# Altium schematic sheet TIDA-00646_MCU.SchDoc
size 431 x 279 mm; Date: Not shown in title block; ApprovedBy: Not shown in title block; CheckedBy: Not shown in title block; Author: Not shown in title block; CompanyName: Not shown in title block; Engineer: Not shown in title block; Organization: Not shown in title block; Address1: Not shown in title block; Address2: Not shown in title block; Address3: Not shown in title block; Address4: Not shown in title block; DocumentNumber: 1; Revision: Use project parameter SCH_Rev; SheetNumber: 2; SheetTotal: 3; PageSetup: Record=PageOptions¦CenterHorizontal=True¦CenterVertical=True¦PrintScale=0.62¦XCorrection=1.00¦YCorrection=1.00¦PrintKind=0¦BorderSize=5000000¦LeftOffset=0¦BottomOffset=0¦Orientation=2¦PaperLength=2794¦PaperWidth=2159¦Scale=100¦PaperSource=7¦PrintQuality=600¦MediaType=1¦DitherType=10¦PrintScaleMode=1¦PaperKind=8 1/2x11¦PaperIndex=1
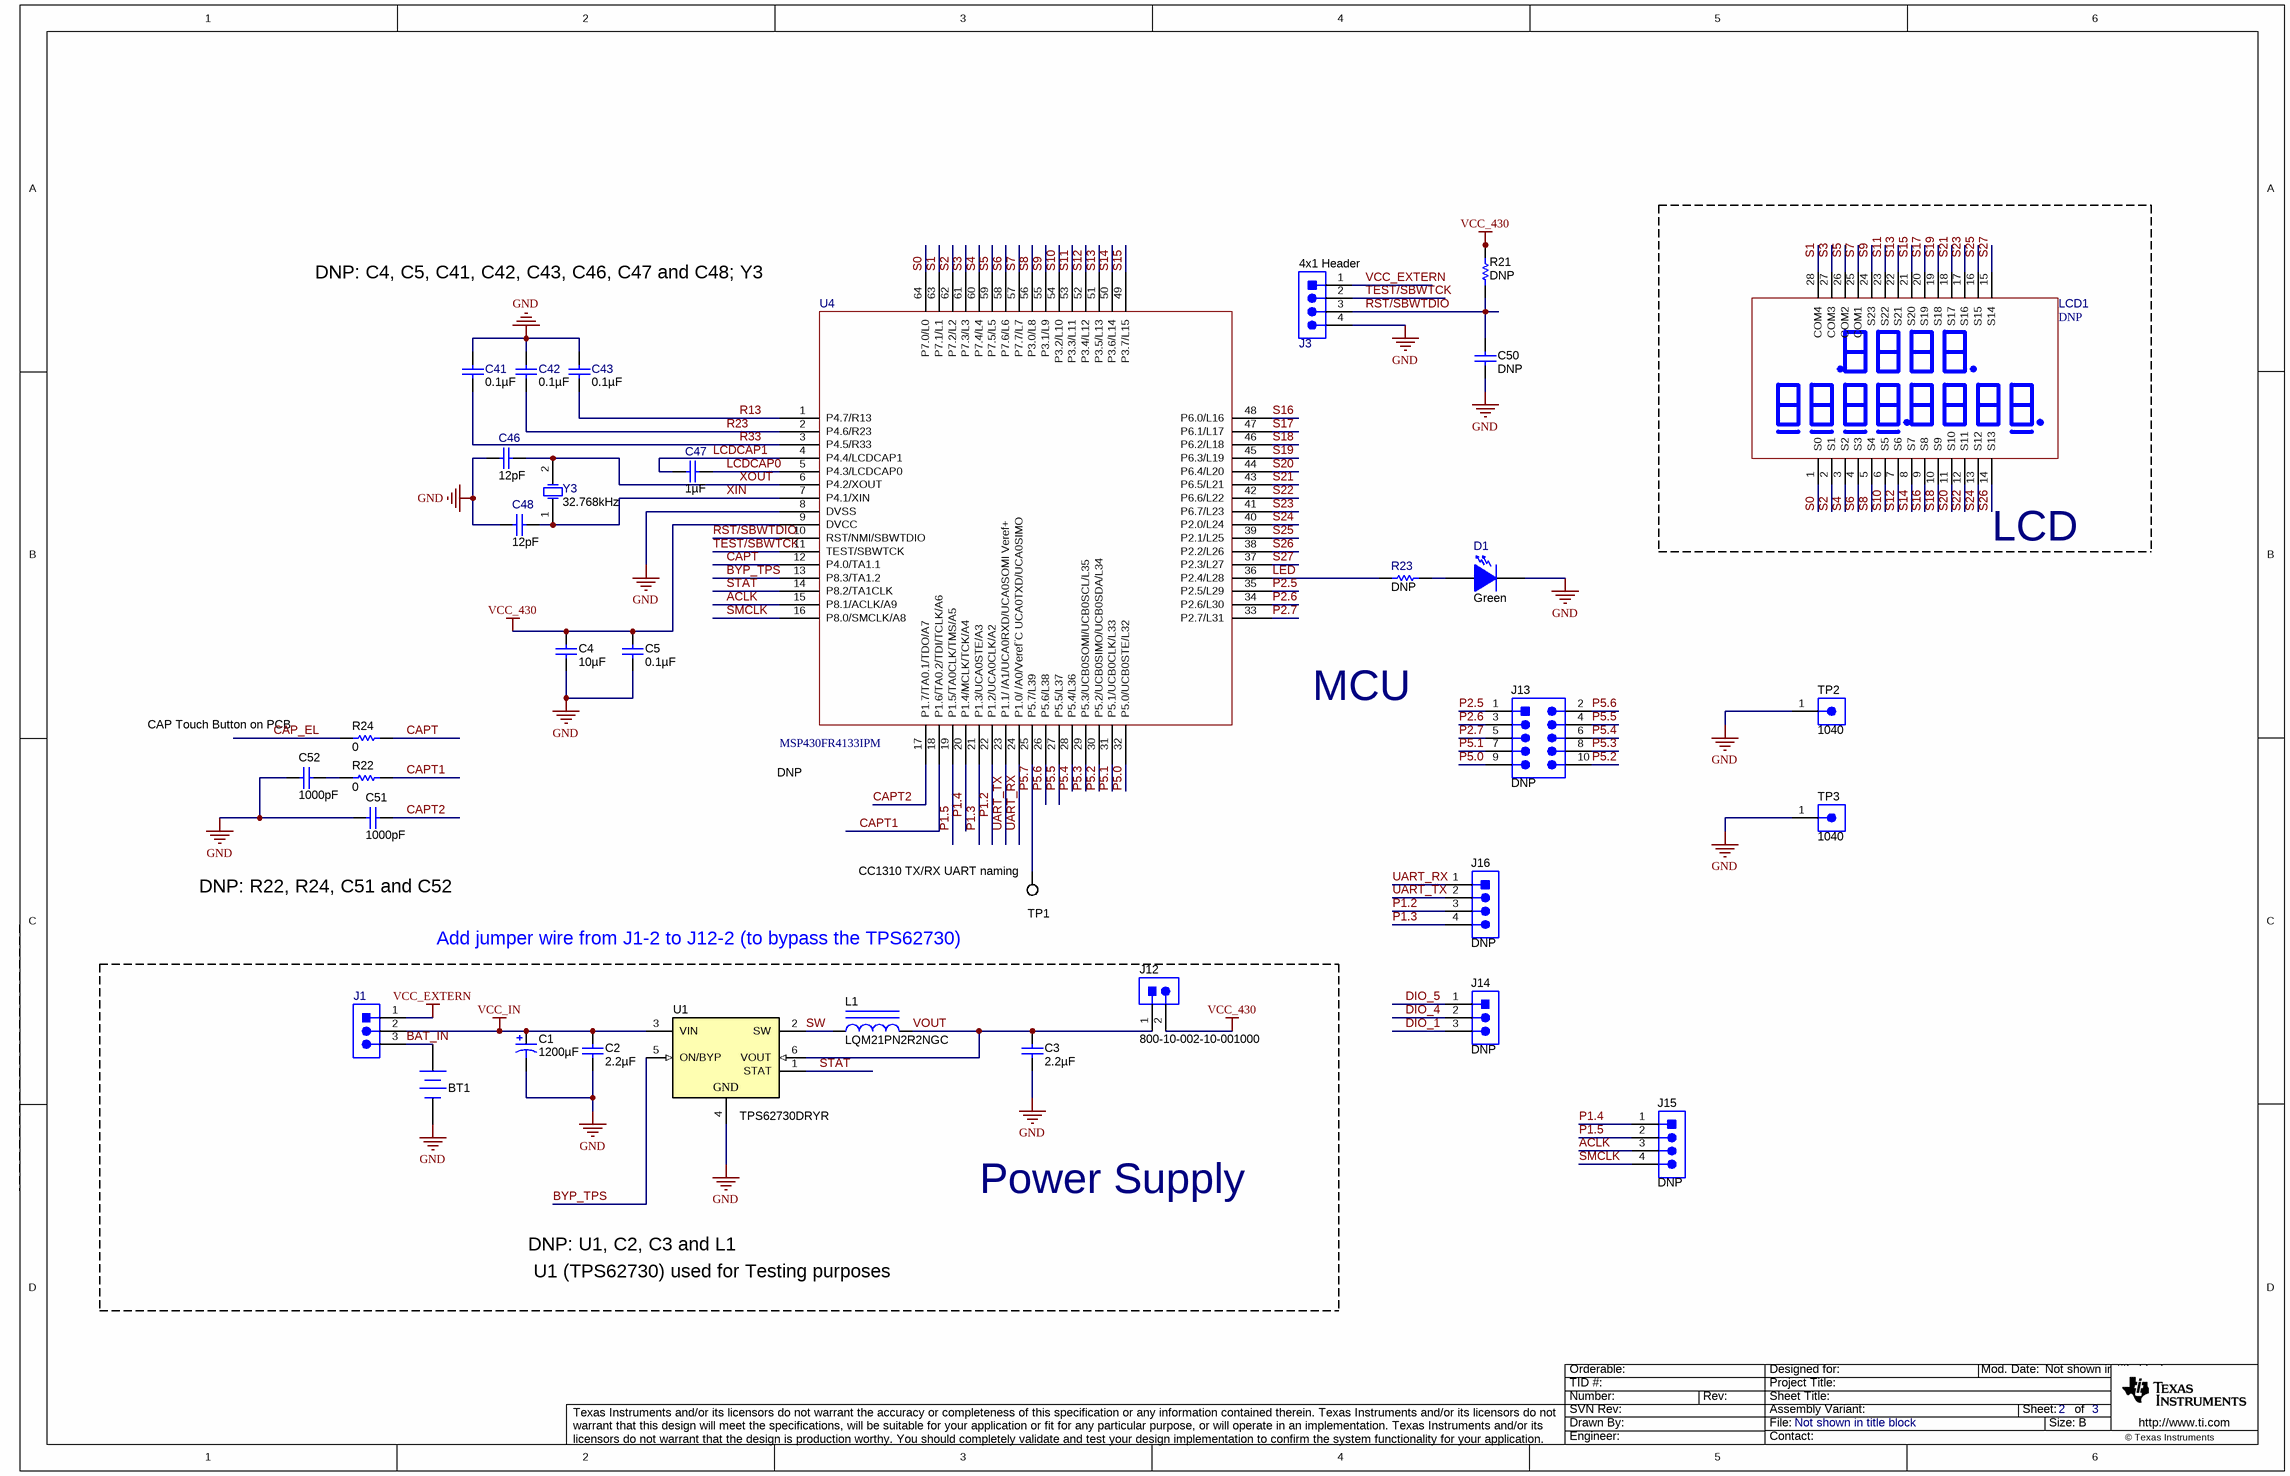
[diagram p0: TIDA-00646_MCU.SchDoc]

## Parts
BT1  1010  [BAT_1010]  (value not drawn)
C1  ValueDisplayed: 1200µF  [CAPPR5-10X20]  (hidden comment: EEUFM1A122)
C2  ValueDisplayed: 2.2µF  [0402]  (hidden comment: GRM155R60J225ME15D)
C3  ValueDisplayed: 2.2µF  [0402]  (hidden comment: GRM155R60J225ME15D)
C4  ValueDisplayed: 10µF  [0603S]  (hidden comment: GRM188R61A106ME69)
C5  ValueDisplayed: 0.1µF  [0402S]  (hidden comment: GRM155R61E104KA87D)
C41  ValueDisplayed: 0.1µF  [0402S]  (hidden comment: GRM155R61E104KA87D)
C42  ValueDisplayed: 0.1µF  [0402S]  (hidden comment: GRM155R61E104KA87D)
C43  ValueDisplayed: 0.1µF  [0402S]  (hidden comment: GRM155R61E104KA87D)
C46  ValueDisplayed: 12pF  [0402S]  (hidden comment: GRM1555C1H120JA01D)
C47  ValueDisplayed: 1µF  [0402S]  (hidden comment: GRM155R61A105KE15D)
C48  ValueDisplayed: 12pF  [0402S]  (hidden comment: GRM1555C1H120JA01D)
C50  ValueDisplayed: DNP  [0402S]  (hidden comment: GRM155R61H102KA01D)
C51  ValueDisplayed: 1000pF  [0402S]  (hidden comment: GRM155R61H102KA01D)
C52  ValueDisplayed: 1000pF  [0402S]  (hidden comment: GRM155R61H102KA01D)
D1  value Green  [LED_LTST-C170]  (hidden comment: LTST-C170KRKT)
J1  TSW-103-07-G-S  [TSW-103-07-G-S]  (value not drawn)
J3  4x1 Header  [TSW-104-07-G-S]
J12  800-10-002-10-001000  [Mill-Max_800-10-002-10-001000]
J13  DNP  [Gradconn_BB02-BS101-xAx-025B00]
J14  DNP  [Mill-Max_850-10-003-10-001000]
J15  DNP  [Preci-dip_850-xx-004-10-001101]
J16  DNP  [Preci-dip_850-xx-004-10-001101]
L1  LQM21PN2R2NGC  [0805_HV]
LCD1  DNP  [LCD]
R21  ValueDisplayed: DNP  [0603S]  (hidden comment: CRCW060347K0JNEA)
R22  ValueDisplayed: 0  [0402S]  (hidden comment: CRCW04020000Z0ED)
R23  ValueDisplayed: DNP  [0603]  (hidden comment: CRCW06031K20JNEA)
R24  ValueDisplayed: 0  [0402S]  (hidden comment: CRCW04020000Z0ED)
TP1  5015  [Testpoint_Keystone_Miniature]  (value not drawn)
TP2  1040  [CONN_1040]
TP3  1040  [CONN_1040]
U1  TPS62730DRYR  [DRY0006A]
U4  PartNumber: MSP430FR4133IPM  [PM0064A_M]  (hidden comment: DNP)
Y3  Frequency: 32.768kHz  [XTAL_MS3V-T1R]  (hidden comment: MS3V-T1R 32.768KHZ +/-20PPM 12.5PF)

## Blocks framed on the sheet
LCD: LCD1
Power Supply: BT1 C1-C3 J1 J12 L1 U1

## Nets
GND: BT1.2(-) C1.2(-) C2.2 C3.2 C4.2 C5.2 C41.1 C42.1 C43.1 C46.1 C48.1 C50.2 C51.1 C52.1 D1.2(K) J3.4 TP2.1 TP3.1 U1.4(GND) U4.8(DVSS)
VCC_430: C4.1 C5.1 J12.2 R21.2 U4.9(DVCC)
VCC_EXTERN: J1.1 J3.1
VCC_IN: C1.1(+) C2.1 J1.2 U1.3(VIN)
ACLK: J15.3 U4.15(P8.1/ACLK/A9)
BAT_IN: BT1.1(+) J1.3
BYP_TPS: U1.5(ON/BYP) U4.13(P8.3/TA1.2)
CAP_EL: R24.1
CAPT: R24.2 U4.12(P4.0/TA1.1)
CAPT1: R22.2 U4.18(P1.6/TA0.2/TDI/TCLK/A6)
CAPT2: C51.2 U4.17(P1.7/TA0.1/TDO/A7)
DIO_1: J14.3
DIO_4: J14.2
DIO_5: J14.1
LCDCAP0: C47.2 U4.5(P4.3/LCDCAP0)
LCDCAP1: C47.1 U4.4(P4.4/LCDCAP1)
LED: R23.1 U4.36(P2.4/L28)
P1.2: J16.3 U4.22(P1.2/UCA0CLK/A2)
P1.3: J16.4 U4.21(P1.3/UCA0STE/A3)
P1.4: J15.1 U4.20(P1.4/MCLK/TCK/A4)
P1.5: J15.2 U4.19(P1.5/TA0CLK/TMS/A5)
P2.5: J13.1 U4.35(P2.5/L29)
P2.6: J13.3 U4.34(P2.6/L30)
P2.7: J13.5 U4.33(P2.7/L31)
P5.0: J13.9 U4.32(P5.0/UCB0STE/L32)
P5.1: J13.7 U4.31(P5.1/UCB0CLK/L33)
P5.2: J13.10 U4.30(P5.2/UCB0SIMO/UCB0SDA/L34)
P5.3: J13.8 U4.29(P5.3/UCB0SOMI/UCB0SCL/L35)
P5.4: J13.6 U4.28(P5.4/L36)
P5.5: J13.4 U4.27(P5.5/L37)
P5.6: J13.2 U4.26(P5.6/L38)
P5.7: TP1.1 U4.25(P5.7/L39)
R13: C43.2 U4.1(P4.7/R13)
R23: C42.2 U4.2(P4.6/R23)
R33: C41.2 U4.3(P4.5/R33)
RST/SBWTDIO: C50.1 J3.3 R21.1 U4.10(RST/NMI/SBWTDIO)
S0: LCD1.1(S0) U4.64(P7.0/L0)
S1: LCD1.28(COM4) U4.63(P7.1/L1)
S2: LCD1.2(S1) U4.62(P7.2/L2)
S3: LCD1.27(COM3) U4.61(P7.3/L3)
S4: LCD1.3(S2) U4.60(P7.4/L4)
S5: LCD1.26(COM2) U4.59(P7.5/L5)
S6: LCD1.4(S3) U4.58(P7.6/L6)
S7: LCD1.25(COM1) U4.57(P7.7/L7)
S8: LCD1.5(S4) U4.56(P3.0/L8)
S9: LCD1.24(S23) U4.55(P3.1/L9)
S10: LCD1.6(S5) U4.54(P3.2/L10)
S11: LCD1.23(S22) U4.53(P3.3/L11)
S12: LCD1.7(S6) U4.52(P3.4/L12)
S13: LCD1.22(S21) U4.51(P3.5/L13)
S14: LCD1.8(S7) U4.50(P3.6/L14)
S15: LCD1.21(S20) U4.49(P3.7/L15)
S16: LCD1.9(S8) U4.48(P6.0/L16)
S17: LCD1.20(S19) U4.47(P6.1/L17)
S18: LCD1.10(S9) U4.46(P6.2/L18)
S19: LCD1.19(S18) U4.45(P6.3/L19)
S20: LCD1.11(S10) U4.44(P6.4/L20)
S21: LCD1.18(S17) U4.43(P6.5/L21)
S22: LCD1.12(S11) U4.42(P6.6/L22)
S23: LCD1.17(S16) U4.41(P6.7/L23)
S24: LCD1.13(S12) U4.40(P2.0/L24)
S25: LCD1.16(S15) U4.39(P2.1/L25)
S26: LCD1.14(S13) U4.38(P2.2/L26)
S27: LCD1.15(S14) U4.37(P2.3/L27)
SMCLK: J15.4 U4.16(P8.0/SMCLK/A8)
STAT: U1.1(STAT) U4.14(P8.2/TA1CLK)
SW: L1.1 U1.2(SW)
TEST/SBWTCK: J3.2 U4.11(TEST/SBWTCK)
UART_RX: J16.1 U4.24(P1.0/_/A0/Veref¨C_UCA0TXD/UCA0SIMO)
UART_TX: J16.2 U4.23(P1.1/_/A1/UCA0RXD/UCA0SOMI_Veref+)
VOUT: C3.1 J12.1 L1.2 U1.6(VOUT)
XIN: C48.2 U4.7(P4.1/XIN) Y3.1(OSC1)
XOUT: C46.2 U4.6(P4.2/XOUT) Y3.2(OSC2)
NetC52_2: C52.2 R22.1
NetD1_1: D1.1(A) R23.2

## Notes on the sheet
- DNP: C4, C5, C41, C42, C43, C46, C47 and C48; Y3
- CAP Touch Button on PCB
- MCU
- DNP: R22, R24, C51 and C52
- (near TP1) CC1310 TX/RX UART naming
- Add jumper wire from J1-2 to J12-2 (to bypass the TPS62730)
- DNP: U1, C2, C3 and L1
- U1 (TPS62730) used for Testing purposes

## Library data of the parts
BT1 = 1010: Battery Holder, Nylon, CR2, SMT; Manufacturer: Keystone
C1 = EEUFM1A122: CAP, AL, 1200 µF, 10 V, +/- 20%, TH; Manufacturer: Panasonic; Polarized: Y; CompType: Capacitor; Value: 1200uF; U/M: EA; Cap_F: 0.0012; Tolerance_%: 20; Value1: Unknown; VDC_V: 10; Value2: 10V; TaMin_C: -40; TaMax_C: 105; Cap_Case: 10x20
C2 C3 = GRM155R60J225ME15D: CAP, CERM, 2.2 µF, 6.3 V, +/- 20%, X5R, 0402; Manufacturer: MuRata; Polarized: N; CompType: Capacitor; Value: 2.2uF; U/M: EA; Cap_F: 0.0000022; Tolerance_%: 20; ESR_ohm: 0.005; Value1: 0.005 ohm; VDC_V: 6.3; Value2: 6.3V; IRMS_A: 3.67; TaMin_C: -55; TaMax_C: 125
C4 = GRM188R61A106ME69: CAP, CERM, 10 µF, 10 V, +/- 20%, X5R, 0603; Manufacturer: MuRata; Polarized: N; CompType: Capacitor; Value: 10uF; U/M: EA; Cap_F: 0.00001; Tolerance_%: 20; Value1: Unknown; VDC_V: 10; Value2: 10V; TaMin_C: -55; TaMax_C: 85; Cap_Case: 0603
C5 C41-C43 = GRM155R61E104KA87D: CAP, CERM, 0.1 µF, 25 V, +/- 10%, X5R, 0402; Manufacturer: MuRata; Polarized: N; CompType: Capacitor; Value: 0.1uF; U/M: EA; Cap_F: 0.0000001; Tolerance_%: 10; Value1: Unknown; VDC_V: 25; Value2: 25V; TaMin_C: -55; TaMax_C: 85; Cap_Case: 0402
C46 C48 = GRM1555C1H120JA01D: CAP, CERM, 12 pF, 50 V, +/- 5%, C0G/NP0, 0402; Manufacturer: MuRata; Polarized: N; CompType: Capacitor; Value: 12pF; U/M: EA; Cap_F: 0.000000000012; Tolerance_%: 5; Value1: Unknown; VDC_V: 50; Value2: 50V; TaMin_C: -55; TaMax_C: 125; Cap_Case: 0402
C47 = GRM155R61A105KE15D: CAP, CERM, 1 µF, 10 V, +/- 10%, X5R, 0402; Manufacturer: MuRata; Polarized: N; CompType: Capacitor; Value: 1uF; U/M: EA; Cap_F: 0.000001; Tolerance_%: 10; Value1: Unknown; Value2: 10V; TaMin_C: -55; TaMax_C: 85; Cap_Case: 0402
C50-C52 = GRM155R61H102KA01D: CAP, CERM, 1000 pF, 50 V, +/- 10%, X5R, 0402; Manufacturer: MuRata; Polarized: N; CompType: Capacitor; Value: 1000pF; U/M: EA; Cap_F: 0.000000001; Tolerance_%: 10; Value1: Unknown; VDC_V: 50; Value2: 50V; TaMin_C: -55; TaMax_C: 85; Cap_Case: 0402
D1 = LTST-C170KRKT: LED, Green, SMD; Manufacturer: Lite-On; Type: AlInGaP; Vf_V: 2; Value2: 2V; Io_A: 20; Value1: W; Color: red; U/M: EA
J1 = TSW-103-07-G-S: Header, TH, 100mil, 3x1, Gold plated, 230 mil above insulator; Manufacturer: Samtec; SymbolCreator: a0799628; U/M: EA
J3 = TSW-104-07-G-S: Header, TH, 100mil, 4x1, Gold plated, 230 mil above insulator; Manufacturer: Samtec; SymbolCreator: a0412235; U/M: EA; Value: DNP
J12 = 800-10-002-10-001000: Header, 100mil, 2x1, TH; Manufacturer: Mill-Max; SymbolCreator: a0412235; U/M: EA
J13 = BB02-BS101-KA8-025B00: Header, 1.27mm, 5x2, SMT; Manufacturer: GradConn; SymbolCreator: a0412235; U/M: EA
J14 = 850-10-003-10-001000: Header, 50mil, 3x1, Gold, TH; Manufacturer: Mill-Max; SymbolCreator: a0799628; U/M: EA
J15 J16 = 850-10-004-10-001101: Header, 50mil, 4x1, Gold, TH; Manufacturer: Preci-Dip; SymbolCreator: a0412235; U/M: EA
L1 = LQM21PN2R2NGC: Inductor, Shielded, Ferrite, 2.2 µH, 0.8 A, 0.23 ohm, SMD; Manufacturer: MuRata; Value: 2.2uH; Ind_H: 2.2E-6; ValueDisplayed: 2.2µH; Imax_A: 0.8; Irms: 0.8A @ 0C rise; DCR_ohm: 0.23; Value2: 0.8A
LCD1 = LCD_4MUX: BTL002 4COM LCD
R21 = CRCW060347K0JNEA: RES, 47 k, 5%, 0.1 W, 0603; Manufacturer: Vishay-Dale; CompType: Resistor; Value: 47k; Res_ohm: 47000; Value_Code: 47k0; Tolerance_%: 5; Power_W: 0.1; Value2: 0.1W; VDC_V: 75; TempCo: 200 ppm/C; EIA_Code: E24; U/M: EA
R22 R24 = CRCW04020000Z0ED: RES, 0, 5%, 0.063 W, 0402; Manufacturer: Vishay-Dale; CompType: Resistor; Value: 0; Value_Code: 0000; Tolerance_%: 5; Power_W: 0.063; Value2: 0.063W; VDC_V: 50; TempCo: 200 ppm/C; EIA_Code: E24; U/M: EA
R23 = CRCW06031K20JNEA: RES, 1.2 k, 5%, 0.1 W, 0603; Manufacturer: Vishay-Dale; CompType: Resistor; Value: 1.2k; Res_ohm: 1200; Value_Code: 1k20; Tolerance_%: 5; Power_W: 0.1; Value2: 0.1W; VDC_V: 75; TempCo: 200 ppm/C; EIA_Code: E24; U/M: EA
TP1 = 5015: Test Point, Miniature, SMT; Manufacturer: Keystone; CompType: Test Point Loop; U/M: EA
TP2 = 1040: TEST POINT SLOTTED .118", TH; Manufacturer: Keystone; CompType: Test Point Loop; U/M: EA; Note: DNP; SymbolCreator: a0412235
TP3 = 1040: TEST POINT SLOTTED .118", TH; Manufacturer: Keystone; CompType: Test Point Loop; U/M: EA; SymbolCreator: a0412235
U1 = TPS62730DRYR: Buck Step Down Regulator with 1.9 to 3.9 V Input and 2.1 V Output, -40 to 85 degC, 6-Pin SON (DRY), Green (RoHS & no Sb/Br); Manufacturer: Texas Instruments; Alternate PartNumber: Equivalent; Duty Cycle(Max)(%): 100; Iout(Max)(A): 0.1; Rating: Catalog; Regulated Outputs(#): 1; SubFamily: Step-Down Regulator; Synchronous Rectification: TRUE; Vin(Max)(V): 3.9; Vin(Min)(V): 1.9; Vout(Max)(V): 2.1
U4 = MSP430G60x1: 16-bit Ultra-Low-Power MCU; Manufacturer: Texas Instruments
Y3 = MS3V-T1R 32.768KHZ +/-20PPM 12.5PF: Crystal, 32.768kHz, 12.5pF, SMD; Manufacturer: Micro Crystal AG; SymbolCreator: a0412235; U/M: EA; TaMin_C: -40; TaMax_C: 85; Frequency Stability: ?0ppm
